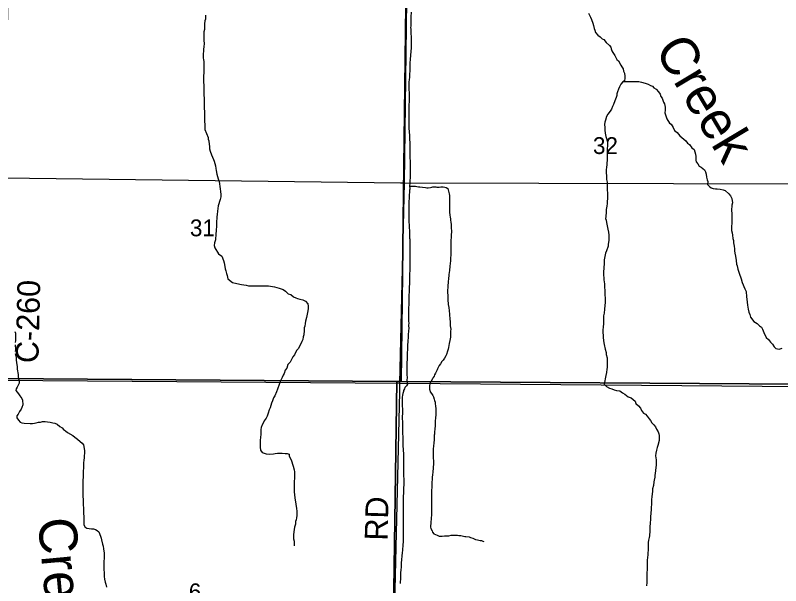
# Model space of a CAD drawing. Extents: x 1588073 to 2013523, y 1090242 to 1357120.
# Drawn here: x 1843684 to 1853753, y 1215583 to 1223082 of the extents above; entities that cross this region are included whole.
import ezdxf

# ---------------------------------------------------------------- set-up
doc = ezdxf.new("R2010")
doc.units = 0
for name, color, linetype in [('GM_X_County_Road', 7, 'Continuous'), ('GM_X_County_Road_Text', 7, 'Continuous'), ('GM_X_Minor_River', 7, 'Continuous'), ('GM_X_Minor_River_Text', 7, 'Continuous'), ('GM_X_Section', 7, 'Continuous'), ('GM_X_Section_Text', 7, 'Continuous'), ('GM_X_Township', 7, 'Continuous'), ('GM_X_Township_Road', 7, 'Continuous')]:
    doc.layers.add(name, color=color, linetype=linetype)

msp = doc.modelspace()

# ---------------------------------------------------------------- linework, layer by layer
at = {"layer": 'GM_X_County_Road'}
for points in [[(1848741, 1218133), (1848744, 1218244), (1848804, 1220879), (1848856, 1224997), (1848857, 1225234), (1848863, 1226144)], [(1848603, 1211895), (1848617, 1212746), (1848741, 1218132), (1848741, 1218133)]]:
    msp.add_lwpolyline(points, dxfattribs=at)
at = {"layer": 'GM_X_Minor_River'}
for points in [[(1846188, 1223083), (1846187, 1223059), (1846185, 1223033), (1846177, 1223009), (1846175, 1222969), (1846173, 1222942), (1846171, 1222918), (1846171, 1222896), (1846163, 1222866), (1846162, 1222824), (1846166, 1222748), (1846168, 1222718), (1846166, 1222664), (1846161, 1222642), (1846161, 1222615), (1846157, 1222573), (1846155, 1222523), (1846159, 1222499), (1846163, 1222477), (1846164, 1222441), (1846166, 1222415), (1846166, 1222355), (1846162, 1222321), (1846158, 1222293), (1846158, 1222268), (1846178, 1221579)], [(1848890, 1223124), (1848888, 1223064), (1848888, 1223036), (1848886, 1223017)], [(1851223, 1223111), (1851251, 1223059), (1851263, 1223027), (1851280, 1222981), (1851288, 1222947), (1851298, 1222908), (1851308, 1222886), (1851316, 1222858), (1851345, 1222820), (1851379, 1222799), (1851403, 1222773), (1851427, 1222765), (1851457, 1222725), (1851500, 1222685), (1851516, 1222663), (1851522, 1222641), (1851530, 1222617), (1851544, 1222595), (1851572, 1222555), (1851597, 1222501), (1851619, 1222483), (1851651, 1222429), (1851665, 1222405), (1851680, 1222379), (1851686, 1222349), (1851698, 1222323), (1851704, 1222281), (1851704, 1222255), (1851698, 1222220), (1851674, 1222208), (1851648, 1222178), (1851633, 1222144), (1851617, 1222112), (1851605, 1222076), (1851599, 1222049), (1851597, 1222027), (1851587, 1222001), (1851571, 1221959), (1851554, 1221909), (1851538, 1221883), (1851526, 1221849), (1851508, 1221820), (1851480, 1221782), (1851462, 1221754), (1851448, 1221706), (1851439, 1221678), (1851437, 1221648), (1851439, 1221607), (1851441, 1221571), (1851443, 1221533), (1851454, 1221489), (1851476, 1221419), (1851476, 1221385)], [(1848886, 1223017), (1848887, 1222999), (1848885, 1222955), (1848885, 1222941), (1848883, 1222923), (1848885, 1222901), (1848885, 1222873), (1848887, 1222847), (1848890, 1222797), (1848892, 1222751), (1848892, 1222705), (1848890, 1222685), (1848890, 1222654), (1848886, 1222608), (1848879, 1222504), (1848875, 1222454), (1848873, 1222402), (1848872, 1222354), (1848868, 1222309), (1848868, 1222269), (1848866, 1222235), (1848862, 1222207), (1848864, 1221964), (1848860, 1221892), (1848861, 1221780), (1848859, 1221734), (1848861, 1221690), (1848861, 1221645), (1848863, 1221599), (1848864, 1221551), (1848868, 1221501), (1848870, 1221451), (1848874, 1221409), (1848875, 1221206), (1848878, 1221168), (1848878, 1221050), (1848877, 1221000), (1848877, 1220950), (1848875, 1220907), (1848873, 1220873), (1848871, 1220845), (1848872, 1220797), (1848870, 1220783), (1848870, 1220755), (1848866, 1220721), (1848866, 1220691), (1848860, 1220623), (1848861, 1220558), (1848859, 1220510), (1848859, 1220438), (1848861, 1220398), (1848866, 1220294), (1848868, 1220247), (1848868, 1220209), (1848871, 1220189), (1848871, 1220153), (1848873, 1220137), (1848874, 1219949), (1848876, 1219903), (1848874, 1219864), (1848874, 1219834), (1848872, 1219804), (1848873, 1219728), (1848871, 1219682), (1848869, 1219634), (1848868, 1219594), (1848868, 1219543), (1848866, 1219523), (1848866, 1219501), (1848864, 1219473), (1848864, 1219441), (1848862, 1219409), (1848861, 1219379), (1848859, 1219349), (1848859, 1219285), (1848857, 1219233), (1848858, 1219060), (1848860, 1219036), (1848858, 1219010), (1848859, 1218958), (1848857, 1218942), (1848855, 1218918), (1848853, 1218900), (1848853, 1218886), (1848851, 1218853), (1848851, 1218837), (1848847, 1218809), (1848846, 1218783), (1848844, 1218755), (1848842, 1218715), (1848838, 1218619), (1848837, 1218583), (1848837, 1218552), (1848835, 1218520), (1848835, 1218442), (1848833, 1218408), (1848834, 1218384), (1848834, 1218368), (1848836, 1218346), (1848838, 1218330), (1848838, 1218310)], [(1851682, 1222212), (1851887, 1222211), (1851923, 1222203), (1851969, 1222192), (1852011, 1222176), (1852041, 1222158), (1852068, 1222150), (1852084, 1222128), (1852114, 1222110), (1852146, 1222076), (1852166, 1222046), (1852178, 1222014), (1852193, 1221992), (1852209, 1221942), (1852225, 1221918), (1852233, 1221876), (1852231, 1221834), (1852230, 1221800), (1852256, 1221722), (1852288, 1221666), (1852311, 1221652), (1852339, 1221606), (1852357, 1221568), (1852389, 1221540), (1852424, 1221500), (1852478, 1221452), (1852506, 1221434), (1852528, 1221402), (1852552, 1221384), (1852585, 1221338), (1852615, 1221318), (1852631, 1221258), (1852637, 1221224), (1852636, 1221178), (1852642, 1221154), (1852664, 1221128), (1852680, 1221098), (1852708, 1221084), (1852752, 1221052), (1852765, 1221024), (1852771, 1220992), (1852777, 1220956), (1852787, 1220918), (1852793, 1220896), (1852788, 1220858), (1852814, 1220832), (1852836, 1220816), (1852866, 1220804), (1852894, 1220800), (1852916, 1220802), (1852958, 1220796), (1852996, 1220788), (1853022, 1220781), (1853069, 1220735), (1853091, 1220711), (1853109, 1220673), (1853117, 1220617), (1853110, 1220588), (1853106, 1220518), (1853108, 1220478), (1853112, 1220402), (1853111, 1220358), (1853107, 1220296), (1853107, 1220251), (1853113, 1220221), (1853120, 1220193), (1853124, 1220147), (1853130, 1220121), (1853134, 1220091), (1853140, 1220047), (1853147, 1220011), (1853147, 1219985), (1853151, 1219957), (1853157, 1219917), (1853165, 1219857), (1853172, 1219812), (1853182, 1219788), (1853190, 1219744), (1853206, 1219692), (1853233, 1219616), (1853245, 1219568), (1853279, 1219486), (1853298, 1219452), (1853304, 1219380), (1853306, 1219352), (1853315, 1219272), (1853325, 1219220), (1853335, 1219179), (1853345, 1219149), (1853355, 1219113), (1853400, 1219057), (1853442, 1219032), (1853474, 1218998), (1853500, 1218980), (1853515, 1218956), (1853529, 1218912), (1853563, 1218846), (1853593, 1218822), (1853618, 1218784), (1853646, 1218758), (1853668, 1218722)], [(1846178, 1221579), (1846221, 1221476), (1846223, 1221452), (1846229, 1221430), (1846233, 1221382), (1846237, 1221360), (1846239, 1221326), (1846248, 1221296), (1846266, 1221248), (1846290, 1221188), (1846298, 1221166), (1846310, 1221132), (1846317, 1221102), (1846321, 1221068), (1846327, 1221044), (1846337, 1220992), (1846352, 1220932), (1846364, 1220898), (1846378, 1220799), (1846384, 1220767), (1846387, 1220725), (1846387, 1220697), (1846381, 1220661), (1846353, 1220579), (1846342, 1220508), (1846340, 1220464), (1846336, 1220432), (1846332, 1220354), (1846329, 1220314), (1846327, 1220251), (1846323, 1220205), (1846323, 1220181), (1846319, 1220155), (1846317, 1220129), (1846306, 1220093), (1846302, 1220055), (1846310, 1220023), (1846359, 1219945), (1846399, 1219915), (1846421, 1219857), (1846433, 1219829), (1846435, 1219807), (1846446, 1219749), (1846454, 1219723), (1846462, 1219689), (1846472, 1219662), (1846482, 1219618), (1846541, 1219571), (1846597, 1219557), (1846659, 1219541), (1846719, 1219533), (1846753, 1219527), (1846808, 1219524), (1846962, 1219524), (1847014, 1219527), (1847092, 1219511), (1847154, 1219497), (1847209, 1219477), (1847237, 1219456), (1847275, 1219422), (1847307, 1219412), (1847343, 1219382), (1847374, 1219368), (1847396, 1219358), (1847428, 1219348), (1847468, 1219340), (1847500, 1219326), (1847532, 1219290), (1847538, 1219258), (1847537, 1219222), (1847529, 1219174), (1847523, 1219152), (1847513, 1219110), (1847501, 1219060), (1847495, 1219032), (1847492, 1218997), (1847486, 1218975), (1847484, 1218939), (1847478, 1218883), (1847472, 1218853), (1847466, 1218821), (1847453, 1218793), (1847437, 1218754), (1847407, 1218696), (1847385, 1218674), (1847357, 1218618), (1847333, 1218590), (1847317, 1218555), (1847298, 1218523), (1847268, 1218489), (1847254, 1218445), (1847236, 1218415), (1847222, 1218372), (1847208, 1218350), (1847194, 1218322), (1847173, 1218276), (1847153, 1218228), (1847133, 1218167), (1847119, 1218131), (1847099, 1218077), (1847079, 1218053)], [(1851476, 1221385), (1851472, 1221315), (1851471, 1221231), (1851469, 1221202), (1851465, 1221114), (1851462, 1221092), (1851458, 1221048), (1851458, 1221018), (1851460, 1220964), (1851462, 1220922), (1851469, 1220890), (1851469, 1220841), (1851471, 1220809), (1851471, 1220781), (1851473, 1220753), (1851475, 1220711), (1851476, 1220677), (1851472, 1220631), (1851468, 1220609), (1851466, 1220573), (1851458, 1220528), (1851456, 1220498), (1851451, 1220434), (1851449, 1220412), (1851455, 1220388), (1851463, 1220360), (1851480, 1220270), (1851488, 1220230), (1851490, 1220190), (1851490, 1220168), (1851492, 1220121), (1851485, 1220075), (1851483, 1220047), (1851463, 1219985), (1851447, 1219953), (1851432, 1219866), (1851430, 1219830), (1851426, 1219754), (1851422, 1219716), (1851422, 1219690), (1851425, 1219606), (1851433, 1219550), (1851435, 1219513), (1851438, 1219459), (1851440, 1219397), (1851444, 1219371), (1851444, 1219343), (1851442, 1219307), (1851439, 1219267), (1851433, 1219219), (1851431, 1219164), (1851423, 1219132), (1851421, 1219094), (1851422, 1219056), (1851420, 1219028), (1851416, 1218988), (1851414, 1218944), (1851414, 1218908), (1851419, 1218876), (1851419, 1218847), (1851421, 1218805), (1851425, 1218775), (1851431, 1218753), (1851445, 1218693), (1851456, 1218649), (1851458, 1218623), (1851468, 1218577), (1851470, 1218531), (1851472, 1218503), (1851471, 1218453), (1851465, 1218429), (1851459, 1218386), (1851453, 1218346), (1851449, 1218324), (1851434, 1218254), (1851430, 1218232), (1851460, 1218202), (1851500, 1218182), (1851532, 1218170), (1851564, 1218156), (1851593, 1218148), (1851635, 1218143), (1851671, 1218119), (1851703, 1218099), (1851747, 1218067), (1851787, 1218055), (1851810, 1218033), (1851840, 1218011), (1851848, 1217979), (1851884, 1217947), (1851910, 1217915), (1851921, 1217887), (1851947, 1217853), (1851975, 1217837), (1851995, 1217813), (1852021, 1217777), (1852041, 1217755), (1852056, 1217725), (1852086, 1217697), (1852106, 1217673), (1852118, 1217639)], [(1848871, 1220837), (1848921, 1220835), (1848950, 1220834), (1848966, 1220830), (1848988, 1220826), (1849004, 1220826), (1849040, 1220824), (1849080, 1220820), (1849098, 1220816), (1849114, 1220816), (1849144, 1220818), (1849162, 1220822), (1849178, 1220827), (1849214, 1220827), (1849230, 1220825), (1849258, 1220825), (1849284, 1220827), (1849314, 1220827), (1849334, 1220825), (1849352, 1220819), (1849373, 1220805), (1849393, 1220735), (1849395, 1220715), (1849396, 1220571), (1849394, 1220537), (1849396, 1220507), (1849396, 1220493), (1849402, 1220453), (1849406, 1220429), (1849411, 1220406), (1849411, 1220390), (1849415, 1220362), (1849417, 1220334), (1849419, 1220302), (1849420, 1220232), (1849418, 1220200), (1849416, 1220162), (1849414, 1220126), (1849414, 1220100), (1849415, 1219947), (1849411, 1219875), (1849409, 1219855), (1849404, 1219817), (1849400, 1219783), (1849394, 1219726), (1849390, 1219702), (1849388, 1219676), (1849381, 1219608), (1849379, 1219590), (1849377, 1219562), (1849375, 1219538), (1849375, 1219512), (1849371, 1219460), (1849372, 1219375), (1849374, 1219345), (1849378, 1219279), (1849386, 1219239), (1849395, 1219155), (1849397, 1219133), (1849401, 1219103), (1849405, 1219039), (1849406, 1219000), (1849412, 1218956), (1849410, 1218930), (1849410, 1218872), (1849408, 1218850), (1849401, 1218806), (1849393, 1218766), (1849381, 1218714), (1849377, 1218691), (1849371, 1218665), (1849357, 1218623), (1849347, 1218607), (1849328, 1218573), (1849314, 1218549), (1849296, 1218529), (1849278, 1218502), (1849262, 1218476), (1849248, 1218452), (1849240, 1218436), (1849232, 1218422), (1849224, 1218402), (1849212, 1218376), (1849200, 1218354), (1849192, 1218338), (1849183, 1218321), (1849171, 1218301), (1849153, 1218273), (1849145, 1218257), (1849139, 1218237), (1849133, 1218211), (1849131, 1218191), (1849131, 1218167), (1849135, 1218153), (1849143, 1218133), (1849158, 1218111), (1849178, 1218083), (1849186, 1218065), (1849196, 1218035), (1849198, 1218019), (1849206, 1217997)], [(1843680, 1218923), (1843686, 1218901), (1843688, 1218873), (1843685, 1218807), (1843683, 1218779)], [(1843683, 1218749), (1843685, 1218690), (1843683, 1218660)], [(1853668, 1218722), (1853690, 1218702), (1853734, 1218694), (1853770, 1218704)], [(1843683, 1218636), (1843690, 1218606), (1843694, 1218580), (1843696, 1218548), (1843700, 1218518), (1843708, 1218462), (1843710, 1218430), (1843715, 1218408), (1843719, 1218382), (1843721, 1218358), (1843721, 1218332), (1843727, 1218302), (1843735, 1218276), (1843733, 1218245), (1843720, 1218221), (1843708, 1218195), (1843696, 1218173), (1843692, 1218151), (1843724, 1218105), (1843744, 1218081), (1843769, 1218043), (1843779, 1218021), (1843783, 1217959), (1843771, 1217927), (1843761, 1217905), (1843741, 1217874), (1843721, 1217838), (1843702, 1217816), (1843702, 1217790), (1843724, 1217758), (1843750, 1217732), (1843772, 1217724), (1843800, 1217720), (1843878, 1217717), (1843912, 1217717), (1843937, 1217719), (1843959, 1217725), (1843991, 1217731), (1844015, 1217733), (1844043, 1217741), (1844077, 1217742), (1844107, 1217738), (1844143, 1217734), (1844177, 1217726), (1844203, 1217720), (1844233, 1217706), (1844271, 1217674), (1844300, 1217658), (1844318, 1217636), (1844346, 1217619), (1844372, 1217599), (1844440, 1217557), (1844465, 1217537), (1844503, 1217509), (1844537, 1217479), (1844563, 1217455), (1844581, 1217433), (1844592, 1217387), (1844594, 1217355), (1844596, 1217325), (1844592, 1217291), (1844590, 1217269), (1844584, 1217227), (1844582, 1217203), (1844581, 1217176), (1844579, 1217128), (1844577, 1217092), (1844575, 1217032), (1844575, 1217004), (1844574, 1216974), (1844574, 1216952), (1844572, 1216912), (1844574, 1216866), (1844574, 1216835), (1844572, 1216805), (1844573, 1216749), (1844575, 1216719), (1844575, 1216643), (1844579, 1216605), (1844580, 1216569), (1844582, 1216527), (1844584, 1216499), (1844586, 1216462), (1844586, 1216436), (1844584, 1216408), (1844585, 1216386), (1844597, 1216358)], [(1848838, 1218310), (1848836, 1218294), (1848836, 1218280), (1848838, 1218250), (1848842, 1218234), (1848828, 1218211), (1848808, 1218187), (1848803, 1218171), (1848791, 1218149), (1848789, 1218135), (1848783, 1218111), (1848777, 1218089), (1848775, 1218061), (1848775, 1217967), (1848774, 1217942), (1848776, 1217908), (1848776, 1217838), (1848774, 1217816), (1848774, 1217768), (1848777, 1217752), (1848777, 1217686), (1848777, 1217652), (1848779, 1217594), (1848780, 1217533), (1848782, 1217497), (1848784, 1217429), (1848784, 1217413), (1848786, 1217381), (1848787, 1217363), (1848789, 1217317), (1848789, 1217243), (1848791, 1217186), (1848792, 1217140), (1848792, 1217104), (1848793, 1216906), (1848791, 1216874), (1848789, 1216833), (1848789, 1216795), (1848788, 1216763), (1848788, 1216713), (1848786, 1216687), (1848786, 1216661), (1848786, 1216567), (1848785, 1216541), (1848785, 1216388), (1848788, 1216364), (1848788, 1216240), (1848786, 1216222), (1848786, 1216206), (1848786, 1216192), (1848785, 1216153), (1848783, 1216125), (1848777, 1216047), (1848775, 1216019), (1848769, 1215971), (1848766, 1215927), (1848762, 1215879), (1848758, 1215832), (1848754, 1215788), (1848752, 1215758), (1848753, 1215744), (1848751, 1215730), (1848751, 1215676), (1848751, 1215660), (1848747, 1215642), (1848745, 1215612)], [(1847079, 1218053), (1847068, 1218013), (1847054, 1217982), (1847036, 1217920), (1847024, 1217896), (1847012, 1217852), (1846997, 1217810), (1846985, 1217786), (1846959, 1217749), (1846947, 1217727), (1846931, 1217697), (1846917, 1217663), (1846913, 1217635), (1846913, 1217595), (1846912, 1217571), (1846908, 1217536), (1846904, 1217494), (1846904, 1217404), (1846911, 1217366), (1846933, 1217336), (1846983, 1217316), (1847031, 1217312), (1847079, 1217317), (1847101, 1217321), (1847135, 1217325), (1847195, 1217325), (1847235, 1217321), (1847262, 1217322), (1847286, 1217310), (1847288, 1217288), (1847314, 1217238), (1847339, 1217153), (1847353, 1217107), (1847355, 1217081), (1847355, 1216999), (1847354, 1216947), (1847354, 1216925), (1847352, 1216887), (1847352, 1216813), (1847356, 1216780), (1847363, 1216734), (1847371, 1216686), (1847379, 1216624), (1847385, 1216600), (1847388, 1216558), (1847386, 1216504), (1847384, 1216474), (1847380, 1216448), (1847372, 1216426), (1847368, 1216391), (1847359, 1216353), (1847349, 1216289), (1847343, 1216253), (1847343, 1216223), (1847345, 1216197), (1847351, 1216169), (1847354, 1216139), (1847354, 1216107)], [(1849206, 1217997), (1849208, 1217973), (1849212, 1217949), (1849215, 1217908), (1849215, 1217828), (1849213, 1217790), (1849209, 1217748), (1849206, 1217684), (1849204, 1217646), (1849200, 1217602), (1849200, 1217577), (1849196, 1217563), (1849195, 1217527), (1849193, 1217499), (1849191, 1217463), (1849187, 1217417), (1849183, 1217383), (1849181, 1217353), (1849180, 1217327), (1849182, 1217297), (1849182, 1217260), (1849184, 1217224), (1849184, 1217184), (1849182, 1217136), (1849177, 1217072), (1849173, 1217046), (1849169, 1217006), (1849167, 1216974), (1849165, 1216947), (1849163, 1216929), (1849162, 1216903), (1849162, 1216871), (1849160, 1216845), (1849160, 1216815), (1849158, 1216769), (1849159, 1216679), (1849157, 1216655), (1849158, 1216506), (1849156, 1216478), (1849156, 1216464), (1849154, 1216450), (1849152, 1216432), (1849152, 1216416), (1849150, 1216394), (1849148, 1216376), (1849148, 1216352), (1849152, 1216334), (1849167, 1216302), (1849173, 1216288), (1849191, 1216266), (1849235, 1216248), (1849259, 1216236), (1849275, 1216234), (1849301, 1216236), (1849331, 1216238), (1849361, 1216240), (1849389, 1216239), (1849419, 1216245), (1849447, 1216249), (1849476, 1216249), (1849500, 1216245), (1849518, 1216243), (1849546, 1216241), (1849598, 1216230), (1849612, 1216228), (1849656, 1216226), (1849672, 1216218), (1849702, 1216206), (1849738, 1216190), (1849762, 1216186), (1849801, 1216178), (1849815, 1216176), (1849833, 1216170), (1849849, 1216164)], [(1852118, 1217639), (1852140, 1217607), (1852151, 1217581), (1852155, 1217557), (1852155, 1217493), (1852135, 1217425), (1852127, 1217399), (1852118, 1217365), (1852108, 1217324), (1852106, 1217290), (1852114, 1217238), (1852114, 1217208), (1852113, 1217168), (1852111, 1217138), (1852103, 1217060), (1852097, 1217034), (1852095, 1217011), (1852089, 1216969), (1852086, 1216947), (1852078, 1216901), (1852068, 1216857), (1852066, 1216827), (1852056, 1216751), (1852053, 1216714), (1852051, 1216654), (1852047, 1216610), (1852047, 1216588), (1852044, 1216532), (1852040, 1216494), (1852040, 1216468), (1852036, 1216397), (1852032, 1216365), (1852029, 1216303), (1852025, 1216239), (1852023, 1216217), (1852013, 1216181), (1852011, 1216151), (1852010, 1216113), (1852010, 1216080), (1852006, 1215984), (1852002, 1215956), (1851997, 1215916), (1851997, 1215858), (1851995, 1215786), (1851993, 1215761), (1851991, 1215733), (1851990, 1215697), (1851990, 1215623), (1851986, 1215581)], [(1844597, 1216358), (1844625, 1216340), (1844655, 1216334), (1844687, 1216331), (1844711, 1216329), (1844737, 1216321), (1844763, 1216309), (1844785, 1216289), (1844804, 1216233), (1844812, 1216209), (1844816, 1216187), (1844832, 1216127), (1844841, 1216101), (1844845, 1216069), (1844851, 1216010), (1844853, 1215974), (1844851, 1215948), (1844850, 1215896), (1844848, 1215874), (1844850, 1215818), (1844850, 1215790), (1844852, 1215756), (1844854, 1215730), (1844855, 1215704), (1844859, 1215669), (1844865, 1215629), (1844873, 1215601), (1844883, 1215565)]]:
    msp.add_lwpolyline(points, dxfattribs=at)
at = {"layer": 'GM_X_Section'}
for points in [[(1843590, 1223612), (1848827, 1223569), (1848760, 1218266), (1848704, 1218266), (1843467, 1218307)], [(1848827, 1223569), (1854141, 1223531), (1854065, 1218234), (1853993, 1218231), (1848760, 1218266)], [(1843467, 1218307), (1848704, 1218266), (1848622, 1212783), (1843407, 1212980)], [(1848704, 1218266), (1848760, 1218266), (1853993, 1218231), (1853945, 1212746), (1848622, 1212783)]]:
    msp.add_lwpolyline(points, close=True, dxfattribs=at)
at = {"layer": 'GM_X_Township'}
for points in [[(1843596, 1223607), (1843525, 1220944), (1843456, 1218285), (1848744, 1218244), (1854040, 1218203)], [(1859011, 1186262), (1853690, 1186324), (1853645, 1186324), (1851014, 1186349), (1848393, 1186378), (1845738, 1186419), (1843068, 1186456), (1843105, 1189507), (1843132, 1191734), (1843209, 1199148), (1843273, 1204127), (1843338, 1209236), (1843390, 1212953), (1843456, 1218285), (1848744, 1218244), (1854040, 1218203)]]:
    msp.add_lwpolyline(points, dxfattribs=at)
at = {"layer": 'GM_X_Township_Road'}
for points in [[(1843525, 1220944), (1848751, 1220879), (1848751, 1220879)], [(1848751, 1220879), (1848804, 1220879), (1854108, 1220867)]]:
    msp.add_lwpolyline(points, dxfattribs=at)

# ---------------------------------------------------------------- texts
at = {"layer": 'GM_X_County_Road_Text'}
for s, rotation, p in [('C-260', 88.6227, (1843987, 1218507)), ('RD', 88.5193, (1848580, 1216173))]:
    msp.add_text(s, height=300, rotation=rotation, dxfattribs=at).set_placement(p)
at = {"layer": 'GM_X_Minor_River_Text'}
for rotation, p in [(300.8617, (1852085, 1222635)), (275.2949, (1843979, 1216458))]:
    msp.add_text('Creek', height=500.3, rotation=rotation, dxfattribs=at).set_placement(p)
at = {"layer": 'GM_X_Section_Text'}
for s, p in [('32', (1851283, 1221259)), ('31', (1845981, 1220177)), ('6', (1845966, 1215392))]:
    msp.add_text(s, height=221, rotation=0, dxfattribs=at).set_placement(p)

doc.saveas('drawing.dxf')
